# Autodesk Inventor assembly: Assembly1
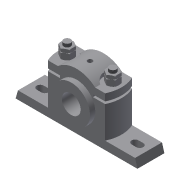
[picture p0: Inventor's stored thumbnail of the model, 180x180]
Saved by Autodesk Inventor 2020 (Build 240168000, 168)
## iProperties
Created: 2015-03
Part Number: Assembly1
Document SubType Name: Assembly
Designer: Sandeep
Author: Sandeep
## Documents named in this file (7)
- D:\Autodesk Inventor_2020\Resources\Resources\Inventor_2020_tut\Inventor_2020_tut\c11_Inv_2020_tut\c11_Inv_tut_2020\c11_tut02_inv\Plummer Block.iam
- D:\Autodesk Inventor_2020\Resources\Resources\Inventor_2020_tut\Inventor_2020_tut\c11_Inv_2020_tut\c11_Inv_tut_2020\c11_tut02_inv\Casting.ipt
- D:\Autodesk Inventor_2020\Resources\Resources\Inventor_2020_tut\Inventor_2020_tut\c11_Inv_2020_tut\c11_Inv_tut_2020\c11_tut02_inv\Brasses.ipt
- D:\Autodesk Inventor_2020\Resources\Resources\Inventor_2020_tut\Inventor_2020_tut\c11_Inv_2020_tut\c11_Inv_tut_2020\c11_tut02_inv\Cap.ipt
- D:\Autodesk Inventor_2020\Resources\Resources\Inventor_2020_tut\Inventor_2020_tut\c11_Inv_2020_tut\c11_Inv_tut_2020\c11_tut02_inv\Bolt.ipt
- D:\Autodesk Inventor_2020\Resources\Resources\Inventor_2020_tut\Inventor_2020_tut\c11_Inv_2020_tut\c11_Inv_tut_2020\c11_tut02_inv\Nut.ipt
- D:\Autodesk Inventor_2020\Resources\Resources\Inventor_2020_tut\Inventor_2020_tut\c11_Inv_2020_tut\c11_Inv_tut_2020\c11_tut02_inv\locknut.ipt
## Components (9 placed, 6 different names)
1. Casting:1 — Mate:1, Mate:2, Insert:1, Insert:2, Angle:1, Angle:2
2. Brasses:1 — Mate:1, Mate:2, Mate:3, Mate:4
3. Cap:1 — Mate:3, Mate:4, Insert:3, Insert:4
4. Bolt:1 — Insert:1, Angle:2
5. Bolt:2 — Insert:2, Angle:1
6. Nut:1 — Insert:3, Insert:5
7. Nut:2 — Insert:4, Insert:6
8. locknut:1 — Insert:5
9. locknut:2 — Insert:6
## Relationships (12: Insert 6, Mate 4, Angle 2)
- Mate:1: Casting:1 ↔ Brasses:1
- Mate:2: Casting:1 ↔ Brasses:1
- Mate:3: Brasses:1 ↔ Cap:1
- Mate:4: Brasses:1 ↔ Cap:1
- Insert:1: Casting:1 ↔ Bolt:1
- Insert:2: Casting:1 ↔ Bolt:2
- Angle:1: Casting:1 ↔ Bolt:2
- Angle:2: Casting:1 ↔ Bolt:1
- Insert:3: Cap:1 ↔ Nut:1
- Insert:4: Cap:1 ↔ Nut:2
- Insert:5: Nut:1 ↔ locknut:1
- Insert:6: Nut:2 ↔ locknut:2
